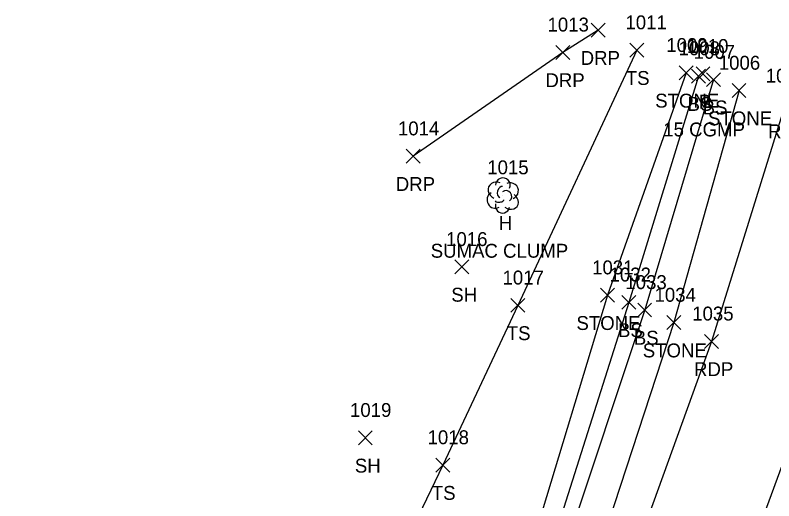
# Model space of a CAD drawing. Extents: x 1599840 to 1601211, y 518904 to 521989.
# Drawn here: x 1600815.1 to 1600924.1, y 521450.4 to 521520.2 of the extents above; entities that cross this region are included whole.
import ezdxf

# ---------------------------------------------------------------- set-up
doc = ezdxf.new("R2010")
doc.units = 0
for name, color, linetype in [('D_A', 7, 'Continuous'), ('D_C', 7, 'Continuous'), ('D_I', 7, 'Continuous'), ('D_TIC', 7, 'Continuous'), ('L_A', 7, 'Continuous'), ('L_C', 7, 'Continuous'), ('L_I', 7, 'Continuous'), ('L_TIC', 7, 'Continuous'), ('LASF', 7, 'Continuous'), ('LELB', 7, 'Continuous'), ('LTD', 7, 'Continuous'), ('P_A', 7, 'Continuous'), ('P_I', 7, 'Continuous'), ('P_TIC', 7, 'Continuous'), ('PET', 7, 'Continuous'), ('PRC', 7, 'Continuous'), ('R_A', 7, 'Continuous'), ('R_I', 7, 'Continuous'), ('R_TIC', 7, 'Continuous'), ('RDP', 7, 'Continuous')]:
    doc.layers.add(name, color=color, linetype=linetype)

msp = doc.modelspace()

# ---------------------------------------------------------------- linework, layer by layer
at = {"layer": 'D_TIC'}
for points in [[(1600912.96, 521510.79), (1600914.96, 521512.79)], [(1600914.96, 521510.79), (1600912.96, 521512.79)]]:
    msp.add_lwpolyline(points, dxfattribs=at)
at = {"layer": 'L_TIC'}
for points in [[(1600903.45, 521514.19), (1600905.45, 521516.19)], [(1600905.45, 521514.19), (1600903.45, 521516.19)], [(1600910.55, 521510.93), (1600912.55, 521512.93)], [(1600912.55, 521510.93), (1600910.55, 521512.93)], [(1600912.3, 521510.46), (1600914.3, 521512.46)], [(1600914.3, 521510.46), (1600912.3, 521512.46)], [(1600914.47, 521509.95), (1600916.47, 521511.95)], [(1600916.47, 521509.95), (1600914.47, 521511.95)], [(1600918.14, 521508.38), (1600920.14, 521510.38)], [(1600920.14, 521508.38), (1600918.14, 521510.38)], [(1600878.29, 521483.02), (1600880.29, 521485.02)], [(1600880.29, 521483.02), (1600878.29, 521485.02)], [(1600899.22, 521478.95), (1600901.22, 521480.95)], [(1600901.22, 521478.95), (1600899.22, 521480.95)], [(1600902.3, 521477.92), (1600904.3, 521479.92)], [(1600904.3, 521477.92), (1600902.3, 521479.92)], [(1600886.34, 521477.49), (1600888.34, 521479.49)], [(1600888.34, 521477.49), (1600886.34, 521479.49)], [(1600904.58, 521476.83), (1600906.58, 521478.83)], [(1600906.58, 521476.83), (1600904.58, 521478.83)], [(1600908.76, 521475.01), (1600910.76, 521477.01)], [(1600910.76, 521475.01), (1600908.76, 521477.01)], [(1600864.43, 521458.44), (1600866.43, 521460.44)], [(1600866.43, 521458.44), (1600864.43, 521460.44)], [(1600875.57, 521454.52), (1600877.57, 521456.52)], [(1600877.57, 521454.52), (1600875.57, 521456.52)]]:
    msp.add_lwpolyline(points, dxfattribs=at)
at = {"layer": 'LASF'}
for points in [[(1600911.55, 521511.93), (1600900.22, 521479.95), (1600889.74, 521445.23), (1600886.89, 521438.48), (1600872.34, 521439.53), (1600863.46, 521422.27), (1600865.41, 521415.76), (1600864.46, 521412.26), (1600859.41, 521407.6), (1600852.7, 521401.77), (1600833.3, 521392.86), (1600833.79, 521390.6)], [(1600919.14, 521509.38), (1600909.76, 521476.01), (1600898.65, 521442.03), (1600883.12, 521403.6), (1600877.59, 521398.68), (1600871.89, 521396.64), (1600869.04, 521399.64), (1600868.64, 521401.06), (1600852.11, 521396.92), (1600833.79, 521390.6)]]:
    msp.add_lwpolyline(points, dxfattribs=at)
at = {"layer": 'LELB'}
for points in [[(1600904.45, 521515.19), (1600887.34, 521478.49), (1600876.57, 521455.52), (1600865.52, 521432.47), (1600859.67, 521425.84), (1600857.51, 521422.34)], [(1600913.3, 521511.46), (1600903.3, 521478.92), (1600892.37, 521444.43), (1600876.87, 521405.75), (1600868.64, 521401.06)], [(1600915.47, 521510.95), (1600905.58, 521477.83), (1600894.08, 521443.3), (1600878.72, 521404.94), (1600869.04, 521399.64), (1600852.73, 521394.05), (1600835.19, 521387.31), (1600828.42, 521384.04)]]:
    msp.add_lwpolyline(points, dxfattribs=at)
at = {"layer": 'LTD'}
msp.add_line((1600885.15, 521494.34), (1600885.15, 521494.34), dxfattribs=at)
msp.add_line((1600885.15, 521494.34), (1600885.15, 521494.34), dxfattribs=at)
msp.add_arc((1600885.2, 521495.77), 1.05, 335.5272, 180.9563, dxfattribs=at)
for centre, major_axis, ratio, start_param, end_param in [((1600884.36, 521495.01), (1.21, -0.51), 0.895232, 1.570796, 4.712389), ((1600886.2, 521494.92), (-1.14, -0.48), 0.949671, 1.570796, 4.712389), ((1600884.95, 521494.8), (-0.208, -0.792), 0.645439, 3.141593, 6.283185), ((1600885.65, 521494.17), (-0.5, 0.667), 0.989748, 3.141593, 6.283185), ((1600884.07, 521493.63), (0.58, -1.04), 0.959034, 3.141593, 6.283185), ((1600886.15, 521493.51), (-1.09, 0.79), 0.841452, 1.570796, 4.712389), ((1600885.15, 521492.84), (0.26, 1.06), 0.942809, 1.570796, 4.712389), ((1600884.7, 521493.59), (-0.625, -0.083), 0.423636, 0, 3.141593)]:
    msp.add_ellipse(centre, major_axis=major_axis, ratio=ratio, start_param=start_param, end_param=end_param, dxfattribs=at)
at = {"layer": 'P_TIC'}
for points in [[(1600914.18, 521472.31), (1600916.18, 521474.31)], [(1600916.18, 521472.31), (1600914.18, 521474.31)]]:
    msp.add_lwpolyline(points, dxfattribs=at)
at = {"layer": 'PET'}
msp.add_lwpolyline([(1600925.83, 521507.52), (1600915.18, 521473.31), (1600903.26, 521440.28), (1600887.48, 521401.44), (1600873.35, 521370.15), (1600860.38, 521343.64), (1600847.93, 521319.69), (1600844.65, 521313.14), (1600836.72, 521299.9), (1600818.79, 521271.51), (1600793.69, 521233.92), (1600774.49, 521208.06), (1600757.09, 521185.54), (1600730.91, 521154.49)], dxfattribs=at)
at = {"layer": 'PRC'}
msp.add_lwpolyline([(1600941.11, 521503.3), (1600929.22, 521466.1), (1600917.95, 521435.49), (1600901.05, 521394.76), (1600888.43, 521365.83), (1600873.97, 521336.55), (1600862.78, 521315.41), (1600848.88, 521291.08), (1600831.54, 521262.94), (1600805.42, 521224.44), (1600786.95, 521198.81), (1600768.67, 521175.32), (1600742.32, 521144.02)], dxfattribs=at)
at = {"layer": 'R_TIC'}
for points in [[(1600897.89, 521517.07), (1600899.89, 521519.07)], [(1600899.89, 521517.07), (1600897.89, 521519.07)], [(1600892.82, 521513.87), (1600894.82, 521515.87)], [(1600894.82, 521513.87), (1600892.82, 521515.87)], [(1600871.31, 521498.94), (1600873.31, 521500.94)], [(1600873.31, 521498.94), (1600871.31, 521500.94)]]:
    msp.add_lwpolyline(points, dxfattribs=at)
at = {"layer": 'RDP'}
msp.add_lwpolyline([(1600898.89, 521518.07), (1600893.82, 521514.87), (1600872.31, 521499.94)], dxfattribs=at)

# ---------------------------------------------------------------- texts
at = {"layer": 'D_A'}
msp.add_text('P', height=2, dxfattribs=at).set_placement((1600913.34, 521506.79))
at = {"layer": 'D_C'}
msp.add_text('15 CGMP', height=2, dxfattribs=at).set_placement((1600908.25, 521502.79))
at = {"layer": 'D_I'}
msp.add_text('1010', height=2, dxfattribs=at).set_placement((1600911.67, 521514.79))
at = {"layer": 'L_A'}
for s, p in [('TS', (1600902.86, 521510.19)), ('STONE', (1600907.09, 521506.93)), ('BS', (1600911.74, 521506.46)), ('BS', (1600913.91, 521505.95)), ('STONE', (1600914.68, 521504.38)), ('H', (1600884.59, 521489.34)), ('SH', (1600877.78, 521479.02)), ('STONE', (1600895.77, 521474.95)), ('TS', (1600885.75, 521473.49)), ('BS', (1600901.74, 521473.92)), ('BS', (1600904.02, 521472.83)), ('STONE', (1600905.3, 521471.01)), ('SH', (1600863.92, 521454.44)), ('TS', (1600874.98, 521450.52))]:
    msp.add_text(s, height=2, dxfattribs=at).set_placement(p)
at = {"layer": 'L_C'}
msp.add_text('SUMAC CLUMP', height=2, dxfattribs=at).set_placement((1600874.82, 521485.34))
at = {"layer": 'L_I'}
for s, p in [('1011', (1600902.81, 521518.19)), ('1009', (1600908.69, 521514.93)), ('1008', (1600910.45, 521514.46)), ('1007', (1600912.62, 521513.95)), ('1006', (1600916.23, 521512.38)), ('1015', (1600882.95, 521497.34)), ('1016', (1600877.03, 521487.02)), ('1031', (1600898.02, 521482.95)), ('1017', (1600885.14, 521481.49)), ('1032', (1600900.53, 521481.92)), ('1033', (1600902.8, 521480.83)), ('1034', (1600906.99, 521479.01)), ('1019', (1600863.22, 521462.44)), ('1018', (1600874.37, 521458.52))]:
    msp.add_text(s, height=2, dxfattribs=at).set_placement(p)
at = {"layer": 'P_A'}
for p in [(1600923.32, 521502.52), (1600912.67, 521468.31)]:
    msp.add_text('RDP', height=2, dxfattribs=at).set_placement(p)
at = {"layer": 'P_I'}
for s, p in [('1005', (1600922.98, 521510.52)), ('1035', (1600912.41, 521476.31))]:
    msp.add_text(s, height=2, dxfattribs=at).set_placement(p)
at = {"layer": 'R_A'}
for p in [(1600896.38, 521513.07), (1600891.31, 521509.87), (1600869.8, 521494.94)]:
    msp.add_text('DRP', height=2, dxfattribs=at).set_placement(p)
at = {"layer": 'R_I'}
for s, p in [('1013', (1600891.61, 521517.87)), ('1014', (1600870.11, 521502.94))]:
    msp.add_text(s, height=2, dxfattribs=at).set_placement(p)

doc.saveas('drawing.dxf')
